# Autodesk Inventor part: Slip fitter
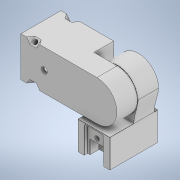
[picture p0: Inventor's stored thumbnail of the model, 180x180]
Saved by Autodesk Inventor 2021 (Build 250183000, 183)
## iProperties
Created: 2020-07
Part Number: Slip fitter
Material: Generic
Document SubType Name: Modeling
Designer: DarrinWoodcock
Density: 1 g/cm^3
Appearance: Default
Title: 000_ASM
Author: Administrator
Sending System: CREO PARAMETRIC BY PTC INC, 2018050
Preprocessor: CREO PARAMETRIC BY PTC INC, 2018050
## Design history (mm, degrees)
feature "0:1"
feature "1:1"
feature "2:1"
feature "3:1"
feature "4:1"
feature "6:1"
feature "7:1"
feature "8:1"
body "Solid1"
body "Solid2"
body "Solid3"
body "Solid4"
body "Solid5"
body "Solid6"
body "Solid7"
body "Solid8"
